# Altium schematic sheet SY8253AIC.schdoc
size 127 x 101 mm
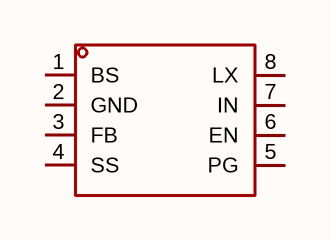
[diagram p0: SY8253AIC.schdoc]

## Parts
U?  sy8253aic  [TSOT-23-8_L2.9-W1.6-P0.65-LS2.8-BL]  (value not drawn)

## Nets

Not connected (* = marked no-connect by the designer): U? 1(BS) 2(GND) 3(FB) 4(SS) 5(PG) 6(EN) 7(IN) 8(LX)

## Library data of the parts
U? = sy8253aic: 功能类型:降压型;工作电压:4.5V~23V;输出电压:-;输出电流:3A;输出类型:可调;; Manufacturer: Silergy(矽力杰); AddInBom: yes; ModelId: dee2381274cf43f7a1d90e9872eb6b7d; ModelName: TSOT-23-8_L2.9-W1.6-H1.1-LS2.8-P0.65; ModelTransform: 110.45568,114.173,0,90,0,0,0,0,0; Function: 降压型; Output Current: 3A; Frequency - Switching: 500kHz; Synchronous Rectifier: 是; Number of Outputs: 1; Topology: 降压式; Quiescent Current: 100uA; Switch tube (built-in/external): 内置; Output Type: 可调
